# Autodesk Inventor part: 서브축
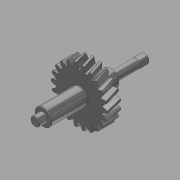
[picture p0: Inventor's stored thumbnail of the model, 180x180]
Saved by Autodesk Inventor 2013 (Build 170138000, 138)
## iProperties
Created: 2017-11
Part Number: 서브축
Material: 강철, 탄소
Document SubType Name: Modeling
Designer: mduedu
Categories: <?xml version="1.0" encoding="UTF-16"?> <MemberInstance><Categories><FamilyTemplate><FamilyTemplateParameter ValueType="xs:double" Id="1" ObjectReferenceKey="da
Density: 7.87 g/cm^3
Mass: 233.397 g
Surface Area: 98.1272 cm^2
Volume: 29.6565 cm^3
CustomPartVersion: 1
Author: mduedu
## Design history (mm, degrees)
sketch "Sketch1"
  geometry: C1 r 24.776 at (0, 0)
  constraints: 1 centre point
  dimensions: "d0" = 49.55215 diameter of C1 (= da_da)
extrude "Extrusion1" new body sketch "Sketch1" distance "d1" = 12 (= da_b); taper "d2" = 0 deg
workplane "Work Plane2"
sketch "Sketch2"
  geometry: C1 r 24.776 at (0, 0) reference; C2 r 22.776 at (0, 0)
  constraints: 1 centre point, 1 coincident
  dimensions: "d3" = 45.55215 diameter of C2 (= da_dw)
feature "피치 지름" sketch "Sketch2" dims "d4" = 10, "d5" = 0
workplane "Work Plane8"
workplane "Work Plane9"
feature "스퍼 기어" dims "da_b" = 12, "da_d" = 45.55215, "da_aw" = 54.86964, "da_da" = 49.55215, "da_df" = 40.55215, "da_dw" = 45.55215, angle "da_beta" = 15 deg, "da_lefttooth" = 10, "da_righttooth" = 0
sketch "스케치3"
  geometry: C1 r 7.5 at (0, 0); 1 further point
  constraints: 1 centre point, 1 coincident
  dimensions: "d49" = 15 diameter of C1
extrude "돌출2" join sketch "스케치3" distance "d50" = 32; taper "d51" = 0 deg
sketch "스케치4"
  geometry: C1 r 4 at (0, 0); 1 further point
  constraints: 1 centre point, 1 coincident
  dimensions: "d52" = 8 diameter of C1
extrude "돌출3" join sketch "스케치4" distance "d53" = 7; taper "d54" = 0 deg
sketch "스케치5"
  geometry: C1 r 7.5 at (0, 0); 1 further point
  constraints: 1 centre point, 1 coincident
  dimensions: "d55" = 15 diameter of C1
extrude "돌출4" join sketch "스케치5" distance "d56" = 16; taper "d57" = 0 deg
sketch "스케치6"
  geometry: C1 r 4 at (0, 0); 1 further point
  constraints: 1 centre point, 1 coincident
  dimensions: "d58" = 8 diameter of C1
extrude "돌출5" join sketch "스케치6" distance "d59" = 30; taper "d60" = 0 deg
chamfer "모따기1" distance "d61" = 0.5; stored, may be unused: second distance "d62" = 2, angle "d63" = 45 deg
fillet "모깎기1" dims "d64" = 0.5
sketch "스케치7"
  geometry: L1 (-3.25, -3.25)-(3.25, -3.25); L2 (3.25, -3.25)-(3.25, 3.25); L3 (3.25, 3.25)-(-3.25, 3.25); L4 (-3.25, 3.25)-(-3.25, -3.25); L5 (-3.25, -3.25)-(3.25, 3.25); L6 (3.25, -3.25)-(-3.25, 3.25); L7 (-5, -5)-(5, -5); L8 (5, -5)-(5, 5); L9 (5, 5)-(-5, 5); L10 (-5, 5)-(-5, -5); L11 (-5, -5)-(5, 5); L12 (5, -5)-(-5, 5); 1 further point
  constraints: 24 end point, 4 midpoint, 4 parallel, 2 horizontal, 2 perpendicular
  dimensions: "d65" = 6.5 distance of L3.end L2.end; "d66" = 6.5 distance of L2.end L1.end; "d67" = 10 distance of L9.end L8.end; "d68" = 10 distance of L8.end L7.end
extrude "돌출6" cut sketch "스케치7" distance "d69" = 8; taper "d70" = 0 deg
body "Solid1"
body "Srf1"
other parameters: "d16" = 54.86964 (= da_aw), "d17" = 0, "d34" = 1.428 (computed from da_z), "d39" = 0, "d41" = 0, "d43" = 54.86964 (= da_aw), "d46" = 54.86964 (= da_aw), "d47" = 0, "d48" = 0
